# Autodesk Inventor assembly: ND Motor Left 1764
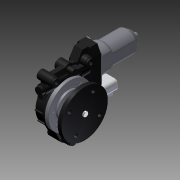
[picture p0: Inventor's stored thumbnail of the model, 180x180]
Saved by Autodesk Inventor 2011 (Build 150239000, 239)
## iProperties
Shininess: 64.0
Length Units: 11272
Angle Units: 11279
Time Units: 11290
Mass Units: 11286
Length Display Precision: 3
Angle Display Precision: 2
Compacted: True
Part Number: ND Motor Left 1764
Document SubType Name: Assembly
Created: 2006-01
Designer: Ed Sparks
Density: 0.0
Volumn: 0.0
Area: 0.0
PropertySet Name: Model Information
Control State: 0
Master: False
Checked Out: False
Author: Ed Sparks
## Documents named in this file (3)
- R:\CAD Archives\Motors\ND Motor Left 1764\ND Motor Left 1764.iam
- R:\CAD Archives\Motors\ND Motor Left 1764\ND Motor Left 1764.ipt
- R:\CAD Archives\Motors\ND Motor Left 1764\Nippon Denso Gear Coupler 2 1764.ipt
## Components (2 placed, 2 different names)
1. ND Motor Left 1764:1 — Mate:1, Angle:1, Mate:2
2. Nippon Denso Gear Coupler 2 1764:1 — Mate:1, Angle:1, Mate:2
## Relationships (3: Mate 2, Angle 1)
- Mate:1: ND Motor Left 1764:1 ↔ Nippon Denso Gear Coupler 2 1764:1
- Angle:1: ND Motor Left 1764:1 ↔ Nippon Denso Gear Coupler 2 1764:1
- Mate:2: ND Motor Left 1764:1 ↔ Nippon Denso Gear Coupler 2 1764:1
